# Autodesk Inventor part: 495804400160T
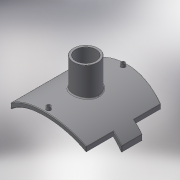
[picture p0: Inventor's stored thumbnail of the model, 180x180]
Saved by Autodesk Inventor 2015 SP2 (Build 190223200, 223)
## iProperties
Created: 2017-10
Part Number: 495804400160T
Material: Generic
Description: PLASSON BRANCH SADDLE 250-400X160
Document SubType Name: Modeling
Designer: KIM
Density: 1 g/cm^3
Appearance: Default
Author: KIM
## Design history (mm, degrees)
derived "495804 (SECOND).ipt"
feature "Solid1::495804 (SECOND).ipt"
tag "TaggingFeature1"
body "Solid1"
other parameters: "d1" = 15, "d2" = 274.5, "d4" = 0, "d5" = 305, "d6" = 75, "d7" = 0, "d8" = 135, "d10" = 0, "d11" = 2, "d12" = 225.6, "d13" = 14, "d14" = 135, "d16" = 5 deg, "d18" = 4, "d19" = 14, "d20" = 0, "d21" = 3, "d22" = 0, "d23" = 334, "d25" = 16, "d26" = 128, "d28" = 0, "d29" = 9.6, "d31" = 0, "d32" = 35.7, "d33" = 0, "d34" = 4, "d35" = 0.8, "B_" = 305, "H_" = 119, "x_" = 15, "D_" = 16
